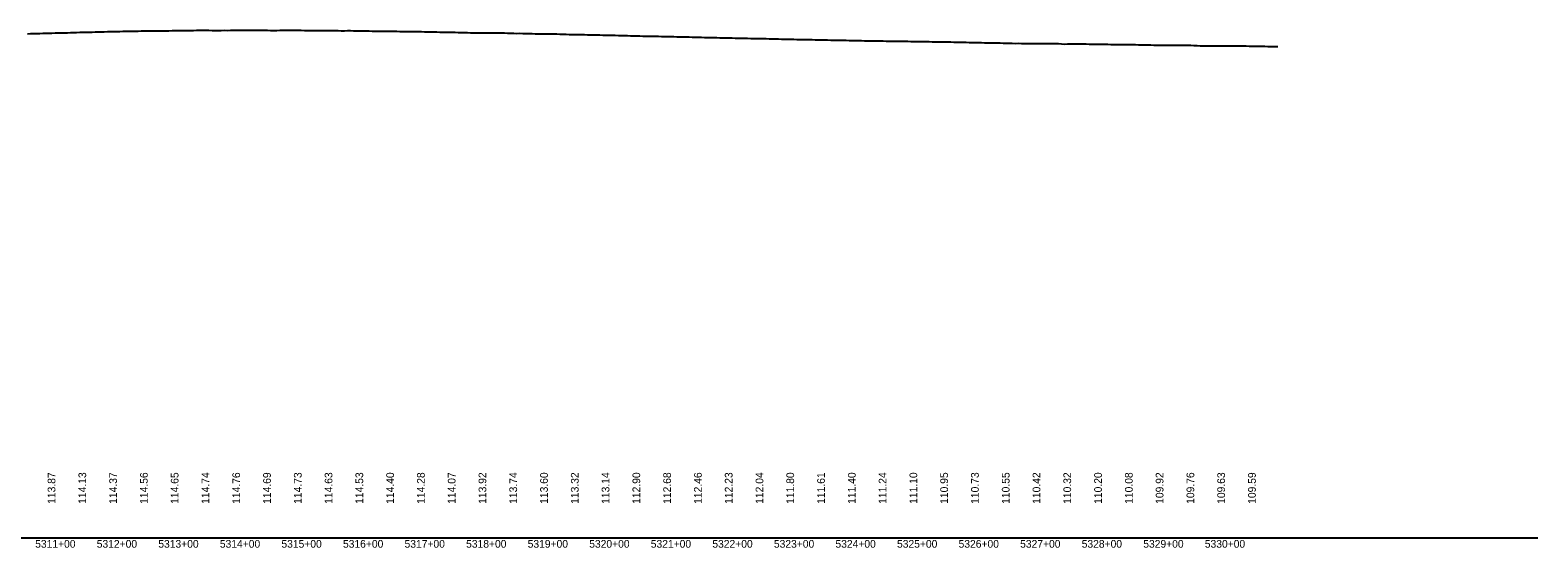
# Model space of a CAD drawing. Extents: x 2147288 to 2220488, y 740833 to 759333.
# Drawn here: x 2163439 to 2165888, y 758067 to 758907 of the extents above; entities that cross this region are included whole.
import ezdxf

# ---------------------------------------------------------------- set-up
doc = ezdxf.new("R2010")
doc.units = 0
for name, color, linetype in [('RD_DDB_Profile_EX', 7, 'Continuous'), ('RD_DDB_StaTX', 7, 'Continuous'), ('RD_DDB_StripGrade', 7, 'Continuous'), ('RD_GPK_Profile_Cell', 7, 'Continuous')]:
    doc.layers.add(name, color=color, linetype=linetype)

msp = doc.modelspace()

# ---------------------------------------------------------------- linework, layer by layer
at = {"layer": 'RD_DDB_Profile_EX'}
for points in [[(2163434.6, 758901.6), (2163439.6, 758901.7), (2163444.6, 758901.8), (2163449.6, 758901.9), (2163454.6, 758902), (2163459.6, 758902.2), (2163464.6, 758902.3), (2163469.6, 758902.5), (2163474.6, 758902.6), (2163479.6, 758902.7), (2163484.6, 758902.8), (2163489.6, 758903), (2163494.6, 758903.1), (2163499.6, 758903.2), (2163504.6, 758903.4), (2163509.6, 758903.5), (2163514.6, 758903.6), (2163519.6, 758903.8), (2163524.6, 758903.9), (2163529.6, 758904), (2163534.6, 758904.2)], [(2163534.6, 758904.2), (2163539.6, 758904.3), (2163544.6, 758904.4), (2163549.6, 758904.5), (2163554.6, 758904.7), (2163559.6, 758904.8), (2163564.6, 758904.9), (2163569.6, 758905), (2163574.6, 758905.1), (2163579.6, 758905.2), (2163584.6, 758905.3), (2163589.6, 758905.5), (2163594.6, 758905.6), (2163599.6, 758905.7), (2163604.6, 758905.7), (2163609.6, 758905.8), (2163614.6, 758905.9), (2163619.6, 758906), (2163624.6, 758906.1), (2163629.6, 758906.2), (2163634.6, 758906.3), (2163639.6, 758906.3), (2163644.6, 758906.4), (2163649.6, 758906.1), (2163654.6, 758906.1), (2163659.6, 758906.2), (2163664.6, 758906.3), (2163669.6, 758906.5), (2163674.6, 758906.6), (2163679.6, 758906.7), (2163684.6, 758906.7), (2163689.6, 758906.8), (2163694.6, 758906.8), (2163699.6, 758906.9), (2163704.6, 758907), (2163709.6, 758907.1), (2163714.6, 758907.1), (2163719.6, 758907.2), (2163724.6, 758907.2), (2163729.6, 758907.2), (2163734.6, 758907), (2163739.6, 758906.7), (2163744.6, 758906.7), (2163749.6, 758907), (2163754.6, 758907.2), (2163759.6, 758907), (2163764.6, 758907.2), (2163769.6, 758907.2), (2163774.6, 758907.2), (2163779.6, 758907.2), (2163784.6, 758907.2), (2163789.6, 758907.2), (2163794.6, 758907.2), (2163799.6, 758907.2), (2163804.6, 758907.2), (2163809.6, 758907.2), (2163814.6, 758907.1), (2163819.6, 758907.1), (2163824.6, 758907.1), (2163829.6, 758906.9), (2163834.6, 758906.8), (2163839.6, 758907), (2163844.6, 758907.2), (2163849.6, 758907.3), (2163854.6, 758907.2), (2163859.6, 758907.2), (2163864.6, 758907.2), (2163869.6, 758907.2), (2163874.6, 758907.1), (2163879.6, 758907.1), (2163884.6, 758907), (2163889.6, 758906.9), (2163894.6, 758906.9), (2163899.6, 758906.8), (2163904.6, 758906.8), (2163909.6, 758906.7), (2163914.6, 758906.7), (2163919.6, 758906.6), (2163924.6, 758906.6), (2163929.6, 758906.6), (2163934.6, 758906.5), (2163939.6, 758906.5), (2163944.6, 758906.4), (2163949.6, 758906.4), (2163954.6, 758906.6), (2163959.6, 758906.5), (2163964.6, 758906.4), (2163969.6, 758906.2), (2163974.6, 758906.2), (2163979.6, 758906.1), (2163984.6, 758906), (2163989.6, 758906), (2163994.6, 758905.9), (2163999.6, 758905.9), (2164004.6, 758905.8), (2164009.6, 758905.7), (2164014.6, 758905.7), (2164019.6, 758905.6), (2164024.6, 758905.5), (2164029.6, 758905.4), (2164034.6, 758905.4)], [(2164034.6, 758905.4), (2164039.6, 758905.3), (2164044.6, 758905.3), (2164049.6, 758905.2), (2164054.6, 758905.2), (2164059.6, 758905.1), (2164064.6, 758905.1), (2164069.6, 758905), (2164074.6, 758904.9), (2164079.6, 758904.8), (2164084.6, 758904.7), (2164089.6, 758904.7), (2164094.6, 758904.5), (2164099.6, 758904.4), (2164104.6, 758904.3), (2164109.6, 758904.2), (2164114.6, 758904.1), (2164119.6, 758904), (2164124.6, 758903.8), (2164129.6, 758903.8), (2164134.6, 758903.7), (2164139.6, 758903.6), (2164144.6, 758903.5), (2164149.6, 758903.3), (2164154.6, 758903.2), (2164159.6, 758903.1), (2164164.6, 758903.1), (2164169.6, 758903.1), (2164174.6, 758903), (2164179.6, 758903), (2164184.6, 758903), (2164189.6, 758903), (2164194.6, 758903), (2164199.6, 758902.9), (2164204.6, 758902.8), (2164209.6, 758902.7), (2164214.6, 758902.5), (2164219.6, 758902.3), (2164224.6, 758902.2), (2164229.6, 758902.1), (2164234.6, 758902.2), (2164239.6, 758902), (2164244.6, 758901.7), (2164249.6, 758902), (2164254.6, 758901.8), (2164259.6, 758901.6), (2164264.6, 758901.5), (2164269.6, 758901.3), (2164274.6, 758901.1), (2164279.6, 758901.5), (2164284.6, 758901.3), (2164289.6, 758901.2), (2164294.6, 758901.1), (2164299.6, 758901), (2164304.6, 758901), (2164309.6, 758900.8), (2164314.6, 758900.5), (2164319.6, 758900.2), (2164324.6, 758900.1), (2164329.6, 758900.1), (2164334.6, 758900), (2164339.6, 758900), (2164344.6, 758899.9), (2164349.6, 758899.8), (2164354.6, 758899.8), (2164359.6, 758899.6), (2164364.6, 758899.5), (2164369.6, 758899.4), (2164374.6, 758899.3), (2164379.6, 758899.2), (2164384.6, 758899), (2164389.6, 758898.9), (2164394.6, 758898.8), (2164399.6, 758898.6), (2164404.6, 758898.5), (2164409.6, 758898.4), (2164414.6, 758898.3), (2164419.6, 758898.2), (2164424.6, 758898.1), (2164429.6, 758898), (2164434.6, 758897.8), (2164439.6, 758897.7), (2164444.6, 758897.6), (2164449.6, 758897.5), (2164454.6, 758897.4), (2164459.6, 758897.3), (2164464.6, 758897.2), (2164469.6, 758897.1), (2164474.6, 758897), (2164479.6, 758896.9), (2164484.6, 758896.8), (2164489.6, 758896.7), (2164494.6, 758896.5), (2164499.6, 758896.4), (2164504.6, 758896.3), (2164509.6, 758896.2), (2164514.6, 758896.1), (2164519.6, 758895.9), (2164524.6, 758895.8), (2164529.6, 758895.7), (2164534.6, 758895.6)], [(2164534.6, 758895.6), (2164539.6, 758895.5), (2164544.6, 758895.4), (2164549.6, 758895.3), (2164554.6, 758895.2), (2164559.6, 758895.1), (2164564.6, 758895), (2164569.6, 758894.8), (2164574.6, 758894.7), (2164579.6, 758894.6), (2164584.6, 758894.5), (2164589.6, 758894.4), (2164594.6, 758894.3), (2164599.6, 758894.2), (2164604.6, 758894.1), (2164609.6, 758894), (2164614.6, 758893.9), (2164619.6, 758893.8), (2164624.6, 758893.7), (2164629.6, 758893.6), (2164634.6, 758893.5), (2164639.6, 758893.4), (2164644.6, 758893.3), (2164649.6, 758893.2), (2164654.6, 758893), (2164659.6, 758892.9), (2164664.6, 758892.8), (2164669.6, 758892.7), (2164674.6, 758892.6), (2164679.6, 758892.5), (2164684.6, 758892.3), (2164689.6, 758892.2), (2164694.6, 758892.1), (2164699.6, 758892.1), (2164704.6, 758892), (2164709.6, 758891.9), (2164714.6, 758891.8), (2164719.6, 758891.7), (2164724.6, 758891.6), (2164729.6, 758891.5), (2164734.6, 758891.4), (2164739.6, 758891.3), (2164744.6, 758891.2), (2164749.6, 758891), (2164754.6, 758891), (2164759.6, 758890.9), (2164764.6, 758890.8), (2164769.6, 758890.7), (2164774.6, 758890.5), (2164779.6, 758890.4), (2164784.6, 758890.3), (2164789.6, 758890.3), (2164794.6, 758890.2), (2164799.6, 758890.2), (2164804.6, 758890.2), (2164809.6, 758890.1), (2164814.6, 758890), (2164819.6, 758889.9), (2164824.6, 758889.8), (2164829.6, 758889.7), (2164834.6, 758889.6), (2164839.6, 758889.5), (2164844.6, 758889.5), (2164849.6, 758889.4), (2164854.6, 758889.3), (2164859.6, 758889.2), (2164864.6, 758889.2), (2164869.6, 758889.1), (2164874.6, 758889), (2164879.6, 758888.9), (2164884.6, 758888.9), (2164889.6, 758888.8), (2164894.6, 758888.8), (2164899.6, 758888.7), (2164904.6, 758888.6), (2164909.6, 758888.5), (2164914.6, 758888.4), (2164919.6, 758888.3), (2164924.6, 758888.3), (2164929.6, 758888.2), (2164934.6, 758888.1), (2164939.6, 758888), (2164944.6, 758887.9), (2164949.6, 758887.9), (2164954.6, 758887.8), (2164959.6, 758887.7), (2164964.6, 758887.5), (2164969.6, 758887.4), (2164974.6, 758887.2), (2164979.6, 758887.1), (2164984.6, 758887), (2164989.6, 758886.9), (2164994.6, 758886.8), (2164999.6, 758886.7), (2165004.6, 758886.7), (2165009.6, 758886.6), (2165014.6, 758886.5), (2165019.6, 758886.4), (2165024.6, 758886.3), (2165029.6, 758886.3), (2165034.6, 758886)], [(2165034.6, 758886), (2165039.6, 758885.9), (2165044.6, 758886), (2165049.6, 758885.9), (2165054.6, 758885.9), (2165059.6, 758885.8), (2165064.6, 758885.7), (2165069.6, 758885.7), (2165074.6, 758885.6), (2165079.6, 758885.5), (2165084.6, 758885.5), (2165089.6, 758885.5), (2165094.6, 758885.4), (2165099.6, 758885.4), (2165104.6, 758885.4), (2165109.6, 758885.4), (2165114.6, 758885.3), (2165119.6, 758884.5), (2165124.6, 758885.3), (2165129.6, 758884.9), (2165134.6, 758885.3), (2165139.6, 758885.2), (2165144.6, 758885.1), (2165149.6, 758885), (2165154.6, 758884.9), (2165159.6, 758884.7), (2165164.6, 758884.7), (2165169.6, 758884.6), (2165174.6, 758884.5), (2165179.6, 758884.4), (2165184.6, 758884.4), (2165189.6, 758884.3), (2165194.6, 758884.2), (2165199.6, 758884.2), (2165204.6, 758884.2), (2165209.6, 758884.1), (2165214.6, 758884), (2165219.6, 758884), (2165224.6, 758883.9), (2165229.6, 758883.9), (2165234.6, 758883.8), (2165239.6, 758883.7), (2165244.6, 758883.6), (2165249.6, 758883.5), (2165254.6, 758883.4), (2165259.6, 758883.3), (2165264.6, 758883.2), (2165269.6, 758883.2), (2165274.6, 758883.1), (2165279.6, 758883), (2165284.6, 758883), (2165289.6, 758883), (2165294.6, 758883), (2165299.6, 758882.9), (2165304.6, 758882.9), (2165309.6, 758882.9), (2165314.6, 758882.9), (2165319.6, 758882.8), (2165324.6, 758882.7), (2165329.6, 758882.2), (2165334.6, 758882.2), (2165339.6, 758882.1), (2165344.6, 758882), (2165349.6, 758881.9), (2165354.6, 758881.9), (2165359.6, 758881.8), (2165364.6, 758881.9), (2165369.6, 758881.9), (2165374.6, 758881.8), (2165379.6, 758881.6), (2165384.6, 758881.6), (2165389.6, 758881.6), (2165394.6, 758881.6), (2165399.6, 758881.8), (2165404.6, 758881.8), (2165409.6, 758881.7), (2165414.6, 758881.6), (2165419.6, 758881.5), (2165424.6, 758881.4), (2165429.6, 758881.4), (2165434.6, 758881.3), (2165439.6, 758881.2), (2165444.6, 758881.1), (2165449.6, 758880.9), (2165454.6, 758880.8), (2165459.6, 758881), (2165464.6, 758881), (2165466.1, 758880.9)]]:
    msp.add_lwpolyline(points, dxfattribs=at)
at = {"layer": 'RD_GPK_Profile_Cell'}
msp.add_line((2148888.3, 758083.4), (2165888.3, 758083.4), dxfattribs=at)

# ---------------------------------------------------------------- texts
at = {"layer": 'RD_DDB_StaTX'}
for s, p in [('5311+00', (2163447.3, 758067.2)), ('5312+00', (2163547.3, 758067.2)), ('5313+00', (2163647.3, 758067.2)), ('5314+00', (2163747.3, 758067.2)), ('5315+00', (2163847.3, 758067.2)), ('5316+00', (2163947.3, 758067.2)), ('5317+00', (2164047.3, 758067.2)), ('5318+00', (2164147.3, 758067.2)), ('5319+00', (2164247.3, 758067.2)), ('5320+00', (2164347.3, 758067.2)), ('5321+00', (2164447.3, 758067.2)), ('5322+00', (2164547.3, 758067.2)), ('5323+00', (2164647.3, 758067.2)), ('5324+00', (2164747.3, 758067.2)), ('5325+00', (2164847.3, 758067.2)), ('5326+00', (2164947.3, 758067.2)), ('5327+00', (2165047.3, 758067.2)), ('5328+00', (2165147.3, 758067.2)), ('5329+00', (2165247.3, 758067.2)), ('5330+00', (2165347.3, 758067.2))]:
    msp.add_text(s, height=12.5, dxfattribs=at).set_placement(p)
at = {"layer": 'RD_DDB_StripGrade'}
for s, p in [('113.87', (2163480.1, 758138.4)), ('114.13', (2163530.1, 758138.4)), ('114.37', (2163580.1, 758138.4)), ('114.56', (2163630.1, 758138.4)), ('114.65', (2163680.1, 758138.4)), ('114.74', (2163730.1, 758138.4)), ('114.76', (2163780.1, 758138.4)), ('114.69', (2163830.1, 758138.4)), ('114.73', (2163880.1, 758138.4)), ('114.63', (2163930.1, 758138.4)), ('114.53', (2163980.1, 758138.4)), ('114.40', (2164030.1, 758138.4)), ('114.28', (2164080.1, 758138.4)), ('114.07', (2164130.1, 758138.4)), ('113.92', (2164180.1, 758138.4)), ('113.74', (2164230.1, 758138.4)), ('113.60', (2164280.1, 758138.4)), ('113.32', (2164330.1, 758138.4)), ('113.14', (2164380.1, 758138.4)), ('112.90', (2164430.1, 758138.4)), ('112.68', (2164480.1, 758138.4)), ('112.46', (2164530.1, 758138.4)), ('112.23', (2164580.1, 758138.4)), ('112.04', (2164630.1, 758138.4)), ('111.80', (2164680.1, 758138.4)), ('111.61', (2164730.1, 758138.4)), ('111.40', (2164780.1, 758138.4)), ('111.24', (2164830.1, 758138.4)), ('111.10', (2164880.1, 758138.4)), ('110.95', (2164930.1, 758138.4)), ('110.73', (2164980.1, 758138.4)), ('110.55', (2165030.1, 758138.4)), ('110.42', (2165080.1, 758138.4)), ('110.32', (2165130.1, 758138.4)), ('110.20', (2165180.1, 758138.4)), ('110.08', (2165230.1, 758138.4)), ('109.92', (2165280.1, 758138.4)), ('109.76', (2165330.1, 758138.4)), ('109.63', (2165380.1, 758138.4)), ('109.59', (2165430.1, 758138.4))]:
    msp.add_text(s, height=12.5, rotation=90, dxfattribs=at).set_placement(p)

doc.saveas('drawing.dxf')
